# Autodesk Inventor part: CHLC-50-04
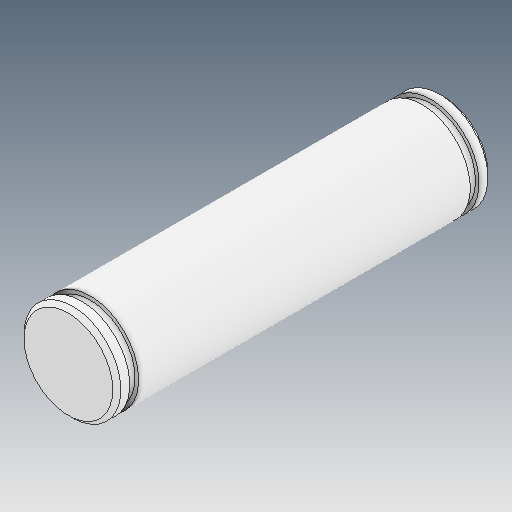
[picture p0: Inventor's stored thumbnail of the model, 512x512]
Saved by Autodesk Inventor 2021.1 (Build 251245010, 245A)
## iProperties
Created: 2021-05
Part Number: CHLC-50-04
Material: Ogólny
Document SubType Name: Modeling
Designer: user
Density: 1 g/cm^3
Appearance: Domyślna
Author: user
Revision Number: ÈÎºÎ
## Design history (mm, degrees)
feature "ÊäÈë1"
node "Bryła1"
